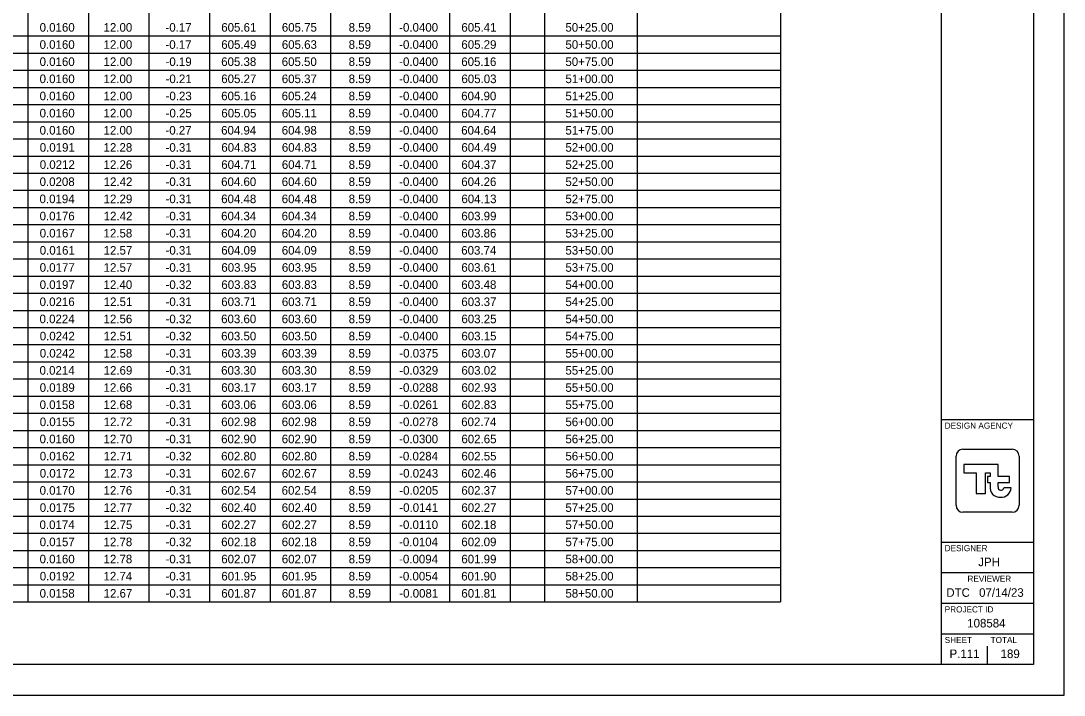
# Model space of a CAD drawing. Extents: x 0 to 34, y 0 to 22.
# Drawn here: x 16.97 to 34, y 0 to 11.01 of the extents above; entities that cross this region are included whole.
import ezdxf

# ---------------------------------------------------------------- set-up
doc = ezdxf.new("R2010")
doc.units = 0
for name, color, linetype in [('Default', 7, 'Continuous'), ('SH_Border', 7, 'Continuous'), ('SH_Cut_Line', 7, 'Continuous'), ('SH_Data', 7, 'Continuous')]:
    doc.layers.add(name, color=color, linetype=linetype)

msp = doc.modelspace()

# ---------------------------------------------------------------- linework, layer by layer
at = {"layer": 'Default'}
for p, q in [((29.368, 20.48), (29.368, 1.522)), ((24.954, 19.376), (24.954, 1.522)), ((27.029, 19.376), (27.029, 1.522)), ((19.057, 18.833), (19.057, 1.522)), ((22.022, 18.833), (22.022, 1.522)), ((25.514, 18.833), (25.514, 1.522)), ((17.081, 18.52), (17.081, 1.522)), ((18.069, 18.52), (18.069, 1.522)), ((20.046, 18.52), (20.046, 1.522)), ((21.034, 18.52), (21.034, 1.522)), ((22.994, 18.52), (22.994, 1.522)), ((23.966, 18.52), (23.966, 1.522)), ((4.135, 10.762), (29.368, 10.762)), ((4.135, 10.482), (29.368, 10.482)), ((4.135, 10.202), (29.368, 10.202)), ((4.135, 9.922), (29.368, 9.922)), ((4.135, 9.642), (29.368, 9.642)), ((4.135, 9.362), (29.368, 9.362)), ((4.135, 9.082), (29.368, 9.082)), ((4.135, 8.802), (29.368, 8.802)), ((4.135, 8.522), (29.368, 8.522)), ((4.135, 8.242), (29.368, 8.242)), ((4.135, 7.962), (29.368, 7.962)), ((4.135, 7.682), (29.368, 7.682)), ((4.135, 7.402), (29.368, 7.402)), ((4.135, 7.122), (29.368, 7.122)), ((4.135, 6.842), (29.368, 6.842)), ((4.135, 6.562), (29.368, 6.562)), ((4.135, 6.282), (29.368, 6.282)), ((4.135, 6.002), (29.368, 6.002)), ((4.135, 5.722), (29.368, 5.722)), ((4.135, 5.442), (29.368, 5.442)), ((4.135, 5.162), (29.368, 5.162)), ((4.135, 4.882), (29.368, 4.882)), ((4.135, 4.602), (29.368, 4.602)), ((4.135, 4.322), (29.368, 4.322)), ((4.135, 4.042), (29.368, 4.042)), ((4.135, 3.762), (29.368, 3.762)), ((4.135, 3.482), (29.368, 3.482)), ((4.135, 3.202), (29.368, 3.202)), ((4.135, 2.922), (29.368, 2.922)), ((4.135, 2.642), (29.368, 2.642)), ((4.135, 2.362), (29.368, 2.362)), ((4.135, 2.082), (29.368, 2.082)), ((4.135, 1.802), (29.368, 1.802)), ((4.135, 1.522), (29.368, 1.522))]:
    msp.add_line(p, q, dxfattribs=at)
at = {"layer": 'SH_Border'}
for p, q in [((32, 0.5), (32, 21.5)), ((32, 4.5), (33.5, 4.5)), ((32, 2.5), (33.5, 2.5)), ((32, 2), (33.5, 2)), ((32, 1.5), (33.5, 1.5)), ((32, 1), (33.5, 1))]:
    msp.add_line(p, q, dxfattribs=at)
msp.add_lwpolyline([(1.5, 21.5), (33.5, 21.5), (33.5, 0.5), (1.5, 0.5)], close=True, dxfattribs=at)
at = {"layer": 'SH_Cut_Line'}
msp.add_lwpolyline([(0, 0), (34, 0), (34, 22), (0, 22)], close=True, dxfattribs=at)
at = {"layer": 'SH_Data'}
for p, q in [((32.75, 3.5), (32.75, 3.5)), ((32.791, 3.415), (32.791, 3.415)), ((33.136, 3.385), (33.015, 3.385)), ((32.75, 0.5), (32.75, 0.8)), ((32.375, 0.675), (32.375, 0.675))]:
    msp.add_line(p, q, dxfattribs=at)
for points in [[(32.348, 4.014), (33.152, 4.014)], [(32.236, 3.099), (32.236, 3.901)], [(32.922, 3.399), (32.922, 3.47), (33.107, 3.47), (33.107, 3.568), (32.922, 3.568), (32.922, 3.768), (32.361, 3.768), (32.361, 3.632), (32.566, 3.632), (32.566, 3.294), (32.715, 3.294), (32.715, 3.63), (32.79, 3.63), (32.79, 3.568), (32.748, 3.568), (32.748, 3.47), (32.79, 3.47), (32.79, 3.415), (32.791, 3.415)], [(33.264, 3.901), (33.264, 3.099)], [(33.152, 2.986), (32.348, 2.986)]]:
    msp.add_lwpolyline(points, dxfattribs=at)
for centre, radius, start, end in [((32.348, 3.901), 0.113, 90, 180), ((33.152, 3.901), 0.113, 360, 90), ((32.949, 3.392), 0.16, 171.8856, 274.8323), ((32.968, 3.392), 0.0473, 171.8856, 350.9243), ((32.976, 3.392), 0.16, 265.1677, 357.3201), ((32.348, 3.099), 0.113, 180, 270), ((33.152, 3.099), 0.113, 270, 360)]:
    msp.add_arc(centre, radius, start, end, dxfattribs=at)

# ---------------------------------------------------------------- texts
at = {"layer": 'Default'}
for s, p in [('0.0160', (17.272, 10.832)), ('12.00', (18.316, 10.832)), ('-0.17', (19.327, 10.832)), ('605.61', (20.238, 10.832)), ('605.75', (21.227, 10.832)), ('8.59', (22.318, 10.832)), ('-0.0400', (23.143, 10.832)), ('605.41', (24.158, 10.832)), ('50+25.00', (25.857, 10.832)), ('0.0160', (17.272, 10.552)), ('12.00', (18.316, 10.552)), ('-0.17', (19.327, 10.552)), ('605.49', (20.238, 10.552)), ('605.63', (21.227, 10.552)), ('8.59', (22.318, 10.552)), ('-0.0400', (23.143, 10.552)), ('605.29', (24.158, 10.552)), ('50+50.00', (25.857, 10.552)), ('0.0160', (17.272, 10.272)), ('12.00', (18.316, 10.272)), ('-0.19', (19.328, 10.272)), ('605.38', (20.237, 10.272)), ('605.50', (21.225, 10.272)), ('8.59', (22.318, 10.272)), ('-0.0400', (23.143, 10.272)), ('605.16', (24.157, 10.272)), ('50+75.00', (25.857, 10.272)), ('0.0160', (17.272, 9.992)), ('12.00', (18.316, 9.992)), ('-0.21', (19.328, 9.992)), ('605.27', (20.238, 9.992)), ('605.37', (21.226, 9.992)), ('8.59', (22.318, 9.992)), ('-0.0400', (23.143, 9.992)), ('605.03', (24.159, 9.992)), ('51+00.00', (25.857, 9.992)), ('0.0160', (17.272, 9.712)), ('12.00', (18.316, 9.712)), ('-0.23', (19.329, 9.712)), ('605.16', (20.237, 9.712)), ('605.24', (21.224, 9.712)), ('8.59', (22.318, 9.712)), ('-0.0400', (23.143, 9.712)), ('604.90', (24.156, 9.712)), ('51+25.00', (25.857, 9.712)), ('0.0160', (17.272, 9.432)), ('12.00', (18.316, 9.432)), ('-0.25', (19.329, 9.432)), ('605.05', (20.239, 9.432)), ('605.11', (21.227, 9.432)), ('8.59', (22.318, 9.432)), ('-0.0400', (23.143, 9.432)), ('604.77', (24.158, 9.432)), ('51+50.00', (25.857, 9.432)), ('0.0160', (17.272, 9.152)), ('12.00', (18.316, 9.152)), ('-0.27', (19.327, 9.152)), ('604.94', (20.236, 9.152)), ('604.98', (21.225, 9.152)), ('8.59', (22.318, 9.152)), ('-0.0400', (23.143, 9.152)), ('604.64', (24.156, 9.152)), ('51+75.00', (25.857, 9.152)), ('0.0191', (17.274, 8.872)), ('12.28', (18.316, 8.872)), ('-0.31', (19.328, 8.872)), ('604.83', (20.239, 8.872)), ('604.83', (21.227, 8.872)), ('8.59', (22.318, 8.872)), ('-0.0400', (23.143, 8.872)), ('604.49', (24.158, 8.872)), ('52+00.00', (25.857, 8.872)), ('0.0212', (17.274, 8.592)), ('12.26', (18.316, 8.592)), ('-0.31', (19.328, 8.592)), ('604.71', (20.238, 8.592)), ('604.71', (21.227, 8.592)), ('8.59', (22.318, 8.592)), ('-0.0400', (23.143, 8.592)), ('604.37', (24.158, 8.592)), ('52+25.00', (25.857, 8.592)), ('0.0208', (17.272, 8.312)), ('12.42', (18.318, 8.312)), ('-0.31', (19.328, 8.312)), ('604.60', (20.236, 8.312)), ('604.60', (21.225, 8.312)), ('8.59', (22.318, 8.312)), ('-0.0400', (23.143, 8.312)), ('604.26', (24.157, 8.312)), ('52+50.00', (25.857, 8.312)), ('0.0194', (17.271, 8.032)), ('12.29', (18.317, 8.032)), ('-0.31', (19.328, 8.032)), ('604.48', (20.237, 8.032)), ('604.48', (21.225, 8.032)), ('8.59', (22.318, 8.032)), ('-0.0400', (23.143, 8.032)), ('604.13', (24.159, 8.032)), ('52+75.00', (25.857, 8.032)), ('0.0176', (17.272, 7.752)), ('12.42', (18.318, 7.752)), ('-0.31', (19.328, 7.752)), ('604.34', (20.236, 7.752)), ('604.34', (21.224, 7.752)), ('8.59', (22.318, 7.752)), ('-0.0400', (23.143, 7.752)), ('603.99', (24.158, 7.752)), ('53+00.00', (25.857, 7.752)), ('0.0167', (17.273, 7.472)), ('12.58', (18.316, 7.472)), ('-0.31', (19.328, 7.472)), ('604.20', (20.236, 7.472)), ('604.20', (21.225, 7.472)), ('8.59', (22.318, 7.472)), ('-0.0400', (23.143, 7.472)), ('603.86', (24.157, 7.472)), ('53+25.00', (25.857, 7.472)), ('0.0161', (17.274, 7.192)), ('12.57', (18.317, 7.192)), ('-0.31', (19.328, 7.192)), ('604.09', (20.238, 7.192)), ('604.09', (21.226, 7.192)), ('8.59', (22.318, 7.192)), ('-0.0400', (23.143, 7.192)), ('603.74', (24.156, 7.192)), ('53+50.00', (25.857, 7.192)), ('0.0177', (17.273, 6.912)), ('12.57', (18.317, 6.912)), ('-0.31', (19.328, 6.912)), ('603.95', (20.239, 6.912)), ('603.95', (21.227, 6.912)), ('8.59', (22.318, 6.912)), ('-0.0400', (23.143, 6.912)), ('603.61', (24.158, 6.912)), ('53+75.00', (25.857, 6.912)), ('0.0197', (17.273, 6.632)), ('12.40', (18.316, 6.632)), ('-0.32', (19.328, 6.632)), ('603.83', (20.239, 6.632)), ('603.83', (21.227, 6.632)), ('8.59', (22.318, 6.632)), ('-0.0400', (23.143, 6.632)), ('603.48', (24.157, 6.632)), ('54+00.00', (25.857, 6.632)), ('0.0216', (17.272, 6.352)), ('12.51', (18.318, 6.352)), ('-0.31', (19.328, 6.352)), ('603.71', (20.238, 6.352)), ('603.71', (21.227, 6.352)), ('8.59', (22.318, 6.352)), ('-0.0400', (23.143, 6.352)), ('603.37', (24.158, 6.352)), ('54+25.00', (25.857, 6.352)), ('0.0224', (17.271, 6.072)), ('12.56', (18.316, 6.072)), ('-0.32', (19.328, 6.072)), ('603.60', (20.236, 6.072)), ('603.60', (21.225, 6.072)), ('8.59', (22.318, 6.072)), ('-0.0400', (23.143, 6.072)), ('603.25', (24.159, 6.072)), ('54+50.00', (25.857, 6.072)), ('0.0242', (17.274, 5.792)), ('12.51', (18.318, 5.792)), ('-0.32', (19.328, 5.792)), ('603.50', (20.236, 5.792)), ('603.50', (21.225, 5.792)), ('8.59', (22.318, 5.792)), ('-0.0400', (23.143, 5.792)), ('603.15', (24.159, 5.792)), ('54+75.00', (25.857, 5.792)), ('0.0242', (17.274, 5.512)), ('12.58', (18.316, 5.512)), ('-0.31', (19.328, 5.512)), ('603.39', (20.238, 5.512)), ('603.39', (21.226, 5.512)), ('8.59', (22.318, 5.512)), ('-0.0375', (23.145, 5.512)), ('603.07', (24.158, 5.512)), ('55+00.00', (25.857, 5.512)), ('0.0214', (17.271, 5.232)), ('12.69', (18.317, 5.232)), ('-0.31', (19.328, 5.232)), ('603.30', (20.236, 5.232)), ('603.30', (21.225, 5.232)), ('8.59', (22.318, 5.232)), ('-0.0329', (23.144, 5.232)), ('603.02', (24.159, 5.232)), ('55+25.00', (25.857, 5.232)), ('0.0189', (17.273, 4.952)), ('12.66', (18.316, 4.952)), ('-0.31', (19.328, 4.952)), ('603.17', (20.238, 4.952)), ('603.17', (21.226, 4.952)), ('8.59', (22.318, 4.952)), ('-0.0288', (23.143, 4.952)), ('602.93', (24.159, 4.952)), ('55+50.00', (25.857, 4.952)), ('0.0158', (17.272, 4.672)), ('12.68', (18.316, 4.672)), ('-0.31', (19.328, 4.672)), ('603.06', (20.237, 4.672)), ('603.06', (21.225, 4.672)), ('8.59', (22.318, 4.672)), ('-0.0261', (23.145, 4.672)), ('602.83', (24.159, 4.672)), ('55+75.00', (25.857, 4.672)), ('0.0155', (17.274, 4.392)), ('12.72', (18.318, 4.392)), ('-0.31', (19.328, 4.392)), ('602.98', (20.237, 4.392)), ('602.98', (21.225, 4.392)), ('8.59', (22.318, 4.392)), ('-0.0278', (23.143, 4.392)), ('602.74', (24.156, 4.392)), ('56+00.00', (25.857, 4.392)), ('0.0160', (17.272, 4.112)), ('12.70', (18.316, 4.112)), ('-0.31', (19.328, 4.112)), ('602.90', (20.236, 4.112)), ('602.90', (21.225, 4.112)), ('8.59', (22.318, 4.112)), ('-0.0300', (23.143, 4.112)), ('602.65', (24.159, 4.112)), ('56+25.00', (25.857, 4.112)), ('0.0162', (17.274, 3.832)), ('12.71', (18.318, 3.832)), ('-0.32', (19.328, 3.832)), ('602.80', (20.236, 3.832)), ('602.80', (21.225, 3.832)), ('8.59', (22.318, 3.832)), ('-0.0284', (23.142, 3.832)), ('602.55', (24.159, 3.832)), ('56+50.00', (25.857, 3.832)), ('0.0172', (17.274, 3.552)), ('12.73', (18.319, 3.552)), ('-0.31', (19.328, 3.552)), ('602.67', (20.238, 3.552)), ('602.67', (21.226, 3.552)), ('8.59', (22.318, 3.552)), ('-0.0243', (23.145, 3.552)), ('602.46', (24.157, 3.552)), ('56+75.00', (25.857, 3.552)), ('0.0170', (17.272, 3.272)), ('12.76', (18.316, 3.272)), ('-0.31', (19.328, 3.272)), ('602.54', (20.236, 3.272)), ('602.54', (21.224, 3.272)), ('8.59', (22.318, 3.272)), ('-0.0205', (23.145, 3.272)), ('602.37', (24.158, 3.272)), ('57+00.00', (25.857, 3.272)), ('0.0175', (17.274, 2.992)), ('12.77', (18.317, 2.992)), ('-0.32', (19.328, 2.992)), ('602.40', (20.236, 2.992)), ('602.40', (21.225, 2.992)), ('8.59', (22.318, 2.992)), ('-0.0141', (23.145, 2.992)), ('602.27', (24.158, 2.992)), ('57+25.00', (25.857, 2.992)), ('0.0174', (17.271, 2.712)), ('12.75', (18.318, 2.712)), ('-0.31', (19.328, 2.712)), ('602.27', (20.238, 2.712)), ('602.27', (21.226, 2.712)), ('8.59', (22.318, 2.712)), ('-0.0110', (23.143, 2.712)), ('602.18', (24.157, 2.712)), ('57+50.00', (25.857, 2.712)), ('0.0157', (17.273, 2.432)), ('12.78', (18.316, 2.432)), ('-0.32', (19.328, 2.432)), ('602.18', (20.237, 2.432)), ('602.18', (21.225, 2.432)), ('8.59', (22.318, 2.432)), ('-0.0104', (23.142, 2.432)), ('602.09', (24.158, 2.432)), ('57+75.00', (25.857, 2.432)), ('0.0160', (17.272, 2.152)), ('12.78', (18.316, 2.152)), ('-0.31', (19.328, 2.152)), ('602.07', (20.238, 2.152)), ('602.07', (21.226, 2.152)), ('8.59', (22.318, 2.152)), ('-0.0094', (23.142, 2.152)), ('601.99', (24.158, 2.152)), ('58+00.00', (25.857, 2.152)), ('0.0192', (17.274, 1.872)), ('12.74', (18.315, 1.872)), ('-0.31', (19.328, 1.872)), ('601.95', (20.239, 1.872)), ('601.95', (21.227, 1.872)), ('8.59', (22.318, 1.872)), ('-0.0054', (23.142, 1.872)), ('601.90', (24.156, 1.872)), ('58+25.00', (25.857, 1.872)), ('0.0158', (17.272, 1.592)), ('12.67', (18.317, 1.592)), ('-0.31', (19.328, 1.592)), ('601.87', (20.238, 1.592)), ('601.87', (21.226, 1.592)), ('8.59', (22.318, 1.592)), ('-0.0081', (23.145, 1.592)), ('601.81', (24.158, 1.592)), ('58+50.00', (25.857, 1.592))]:
    msp.add_text(s, height=0.14, dxfattribs=at).set_placement(p)
at = {"layer": 'SH_Data'}
for s, height, p in [('DESIGN AGENCY', 0.1, (32.05, 4.35)), ('DESIGNER', 0.1, (32.05, 2.35)), ('JPH', 0.14, (32.598, 2.105)), ('REVIEWER', 0.1, (32.422, 1.85)), ('DTC', 0.14, (32.076, 1.605)), ('07/14/23', 0.14, (32.611, 1.605)), ('PROJECT ID', 0.1, (32.05, 1.35)), ('108584', 0.14, (32.418, 1.105)), ('SHEET', 0.1, (32.05, 0.85)), ('TOTAL', 0.1, (32.8, 0.85)), ('P.111', 0.14, (32.129, 0.605)), ('189', 0.14, (32.963, 0.605))]:
    msp.add_text(s, height=height, dxfattribs=at).set_placement(p)

doc.saveas('drawing.dxf')
